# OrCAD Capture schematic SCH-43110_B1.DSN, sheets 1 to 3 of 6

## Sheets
1 5.Sensor, CAN, LIN,  Misc: size C; title: X-FRDM-KW38A; rev: B1; company: NXP Semiconductors; note: SCH-43110_B PDF: SPF-43110_B; note: 6501 William Cannon Drive West; note: Austin, TX 78735-8598
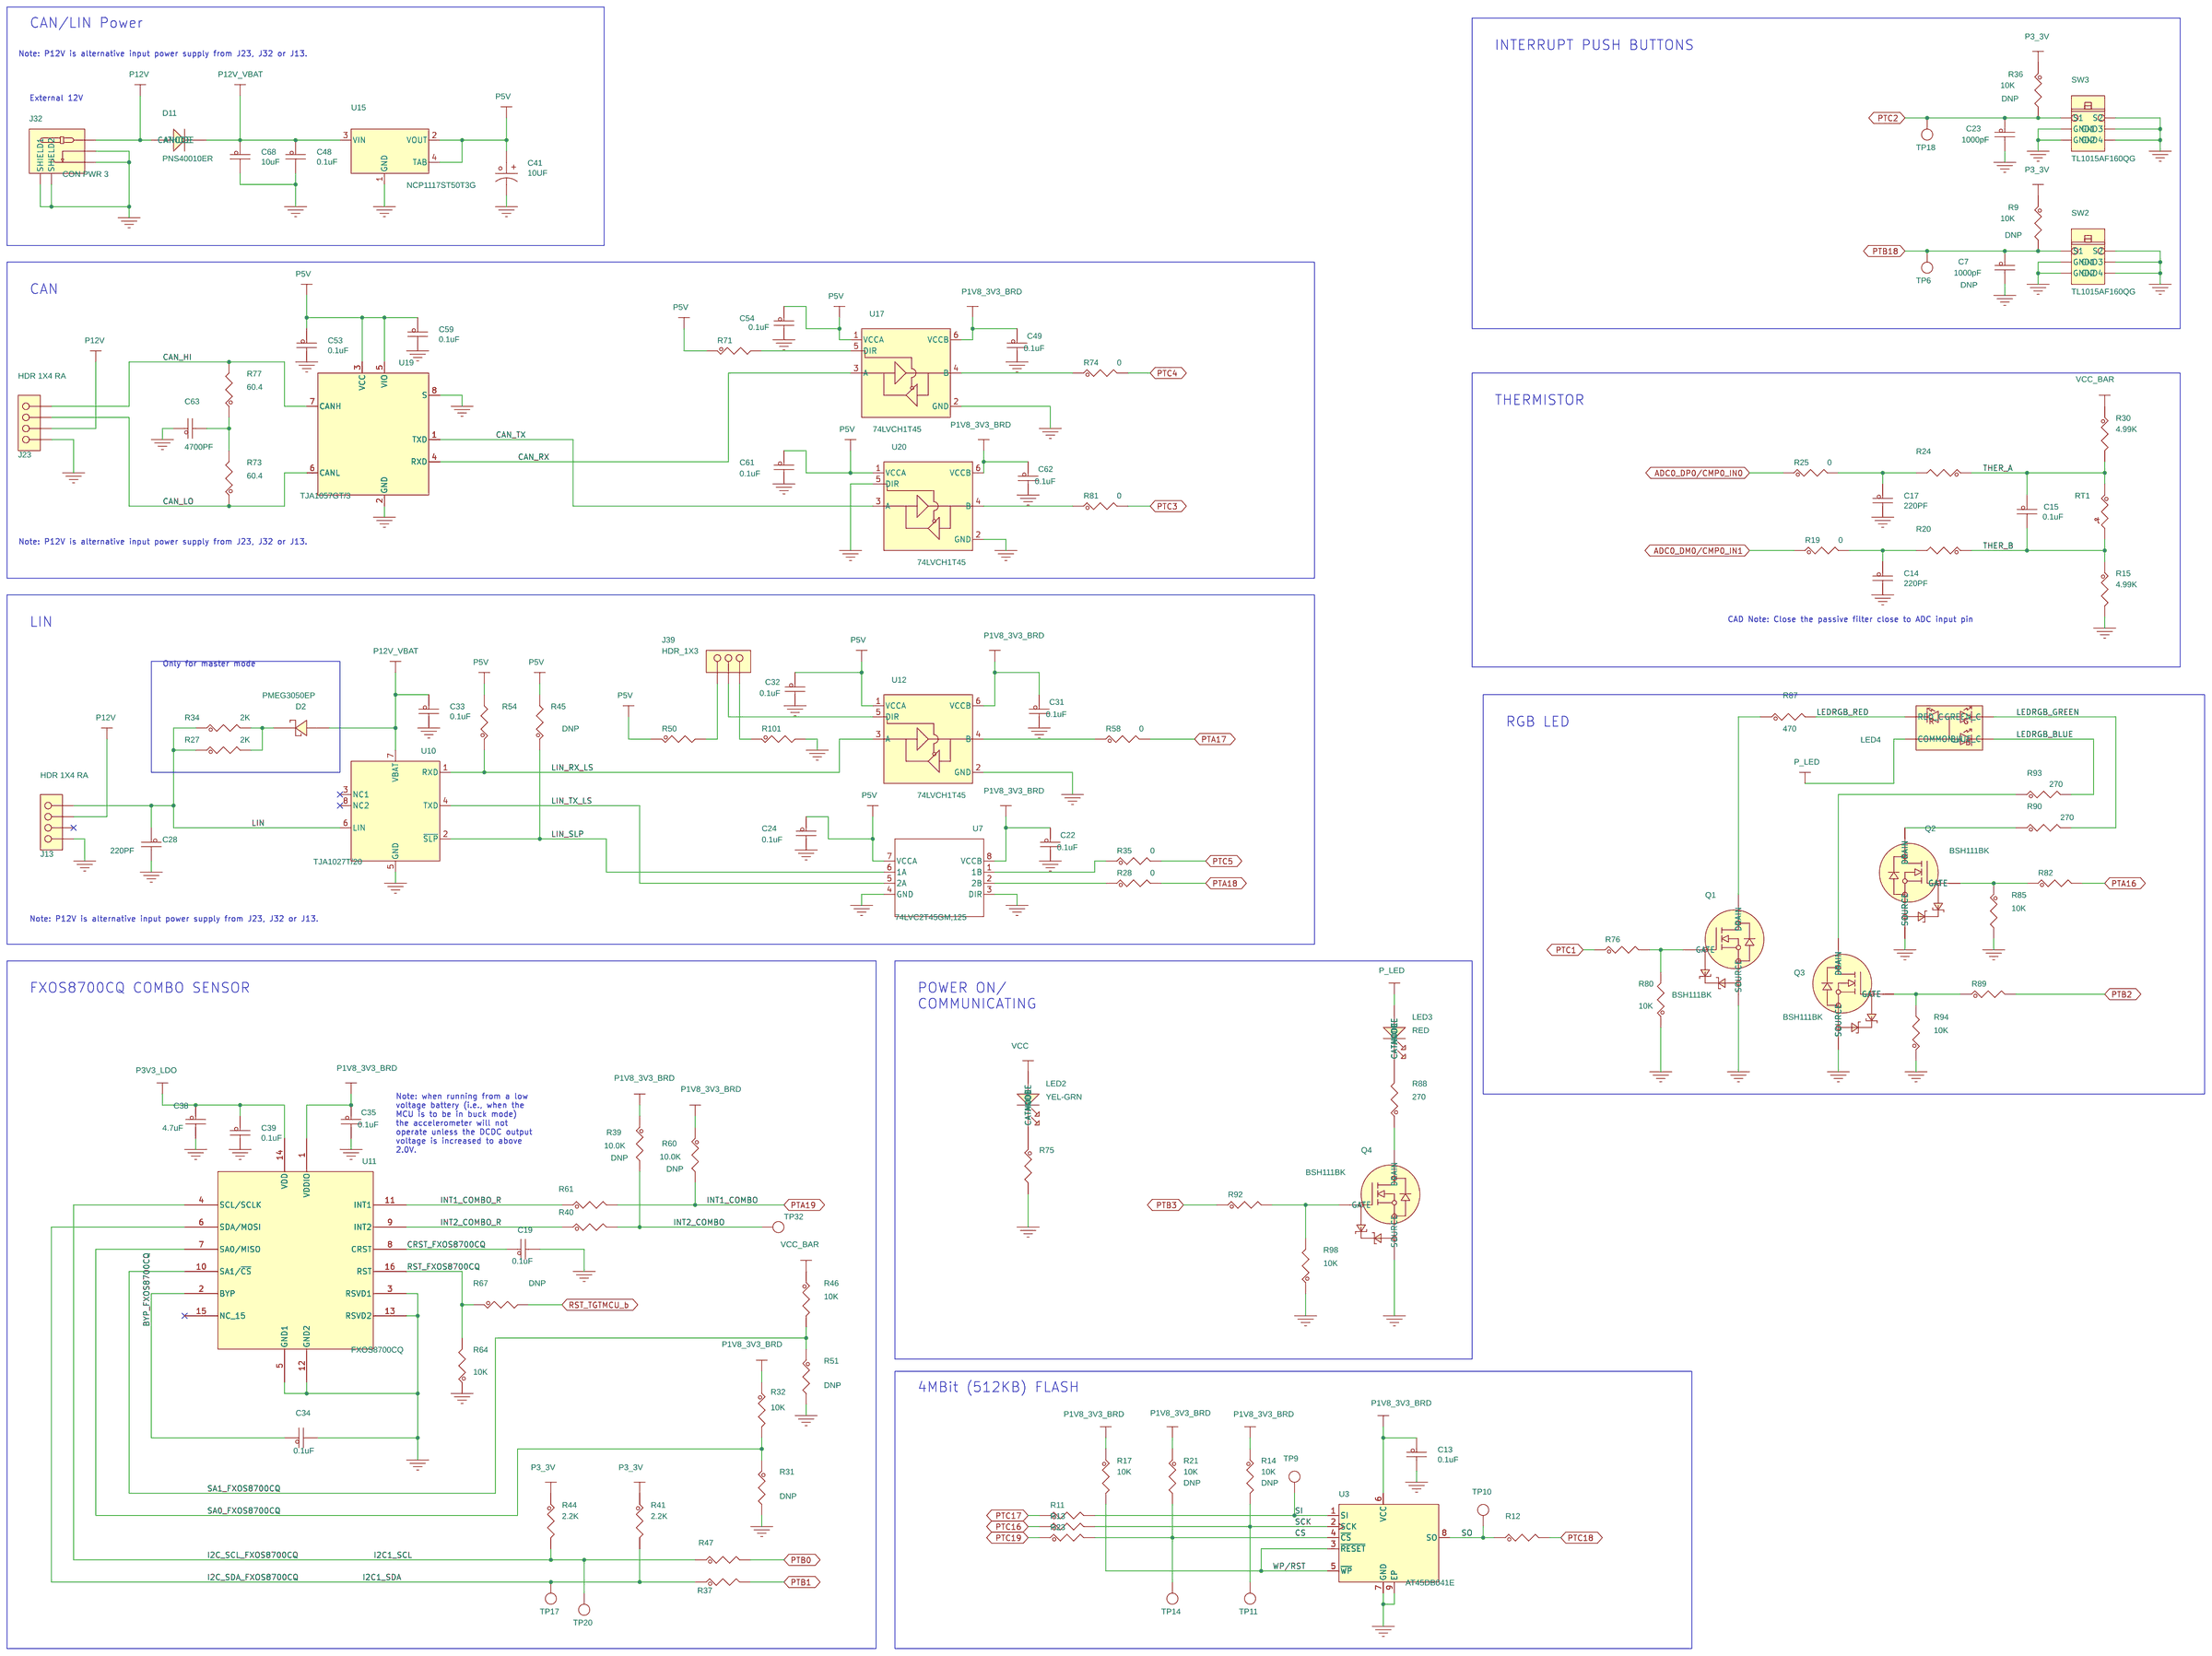
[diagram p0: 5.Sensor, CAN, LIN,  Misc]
2 1. Title Page
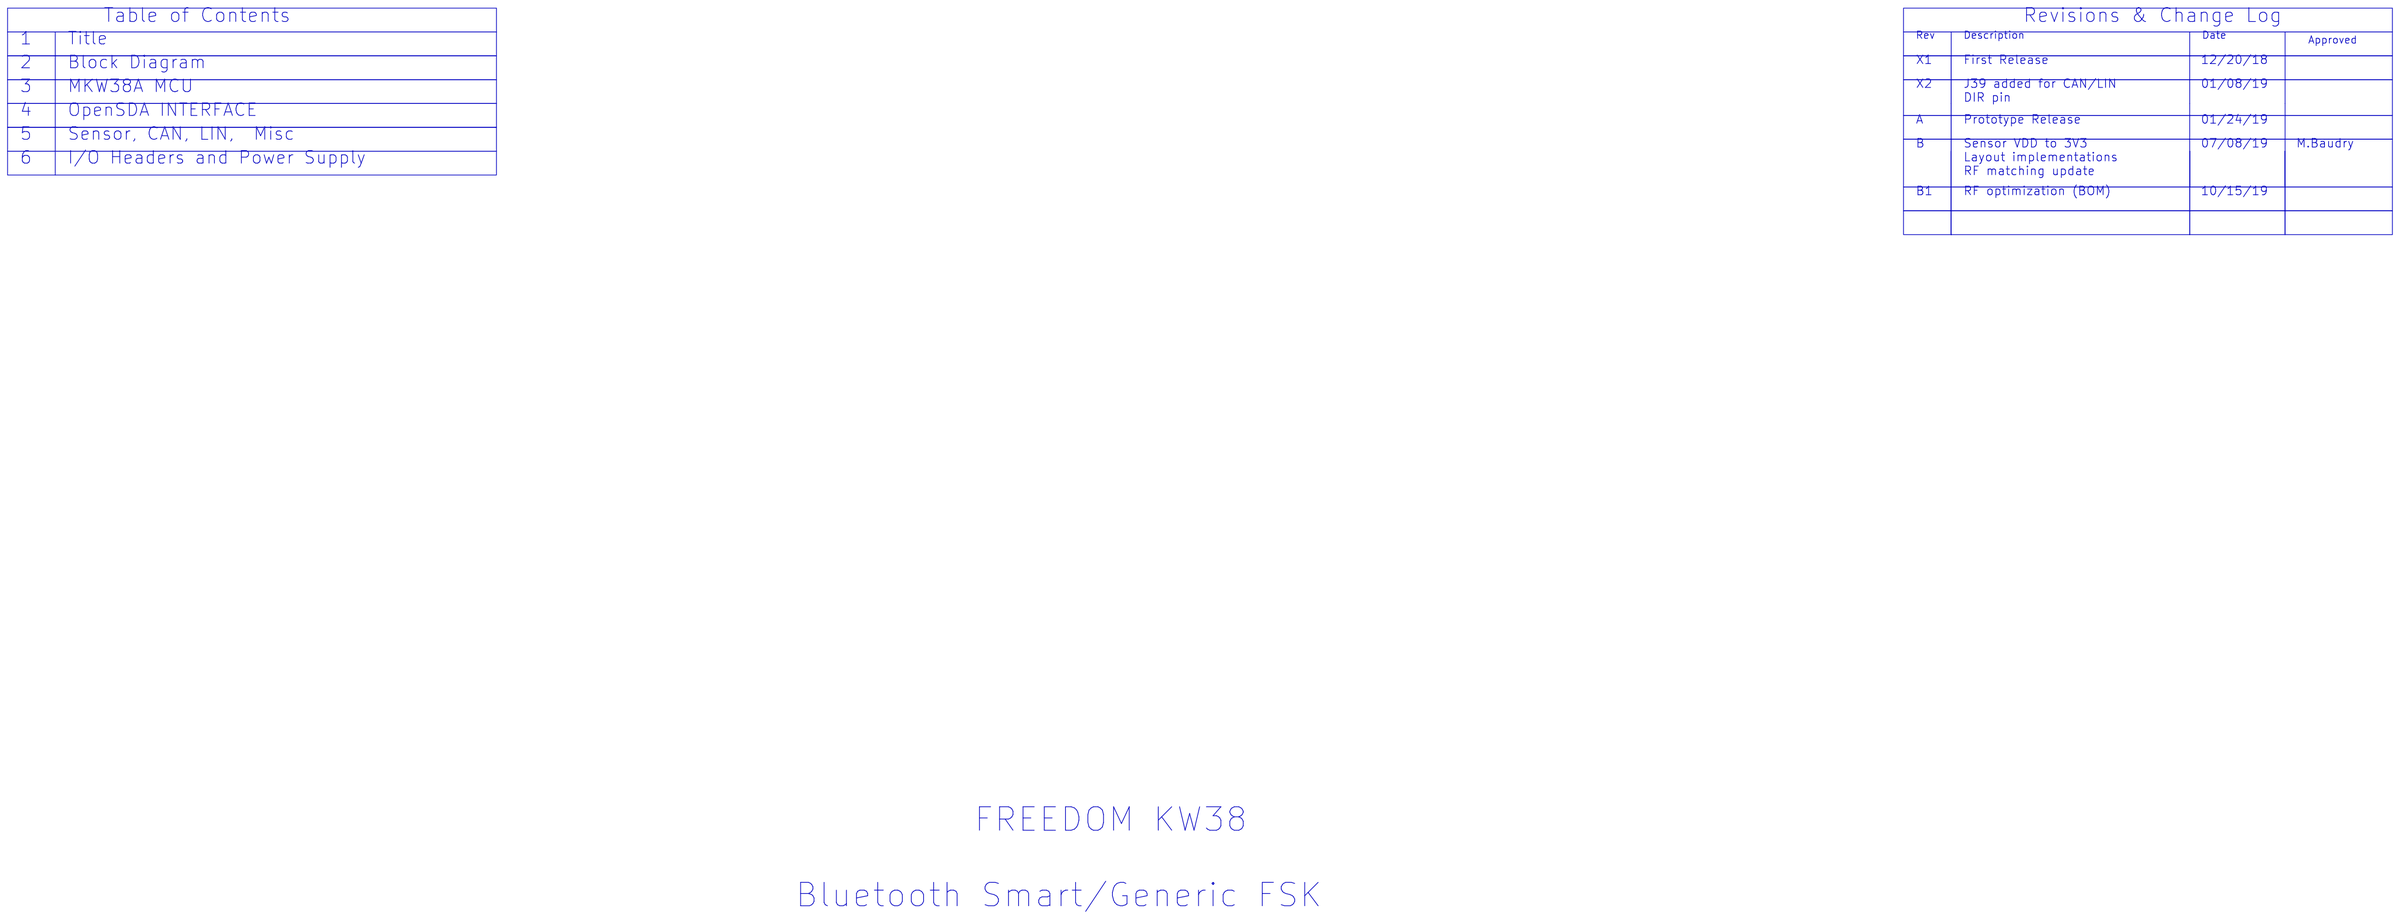
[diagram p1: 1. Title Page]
3 4. OpenSDA interface: size Custom
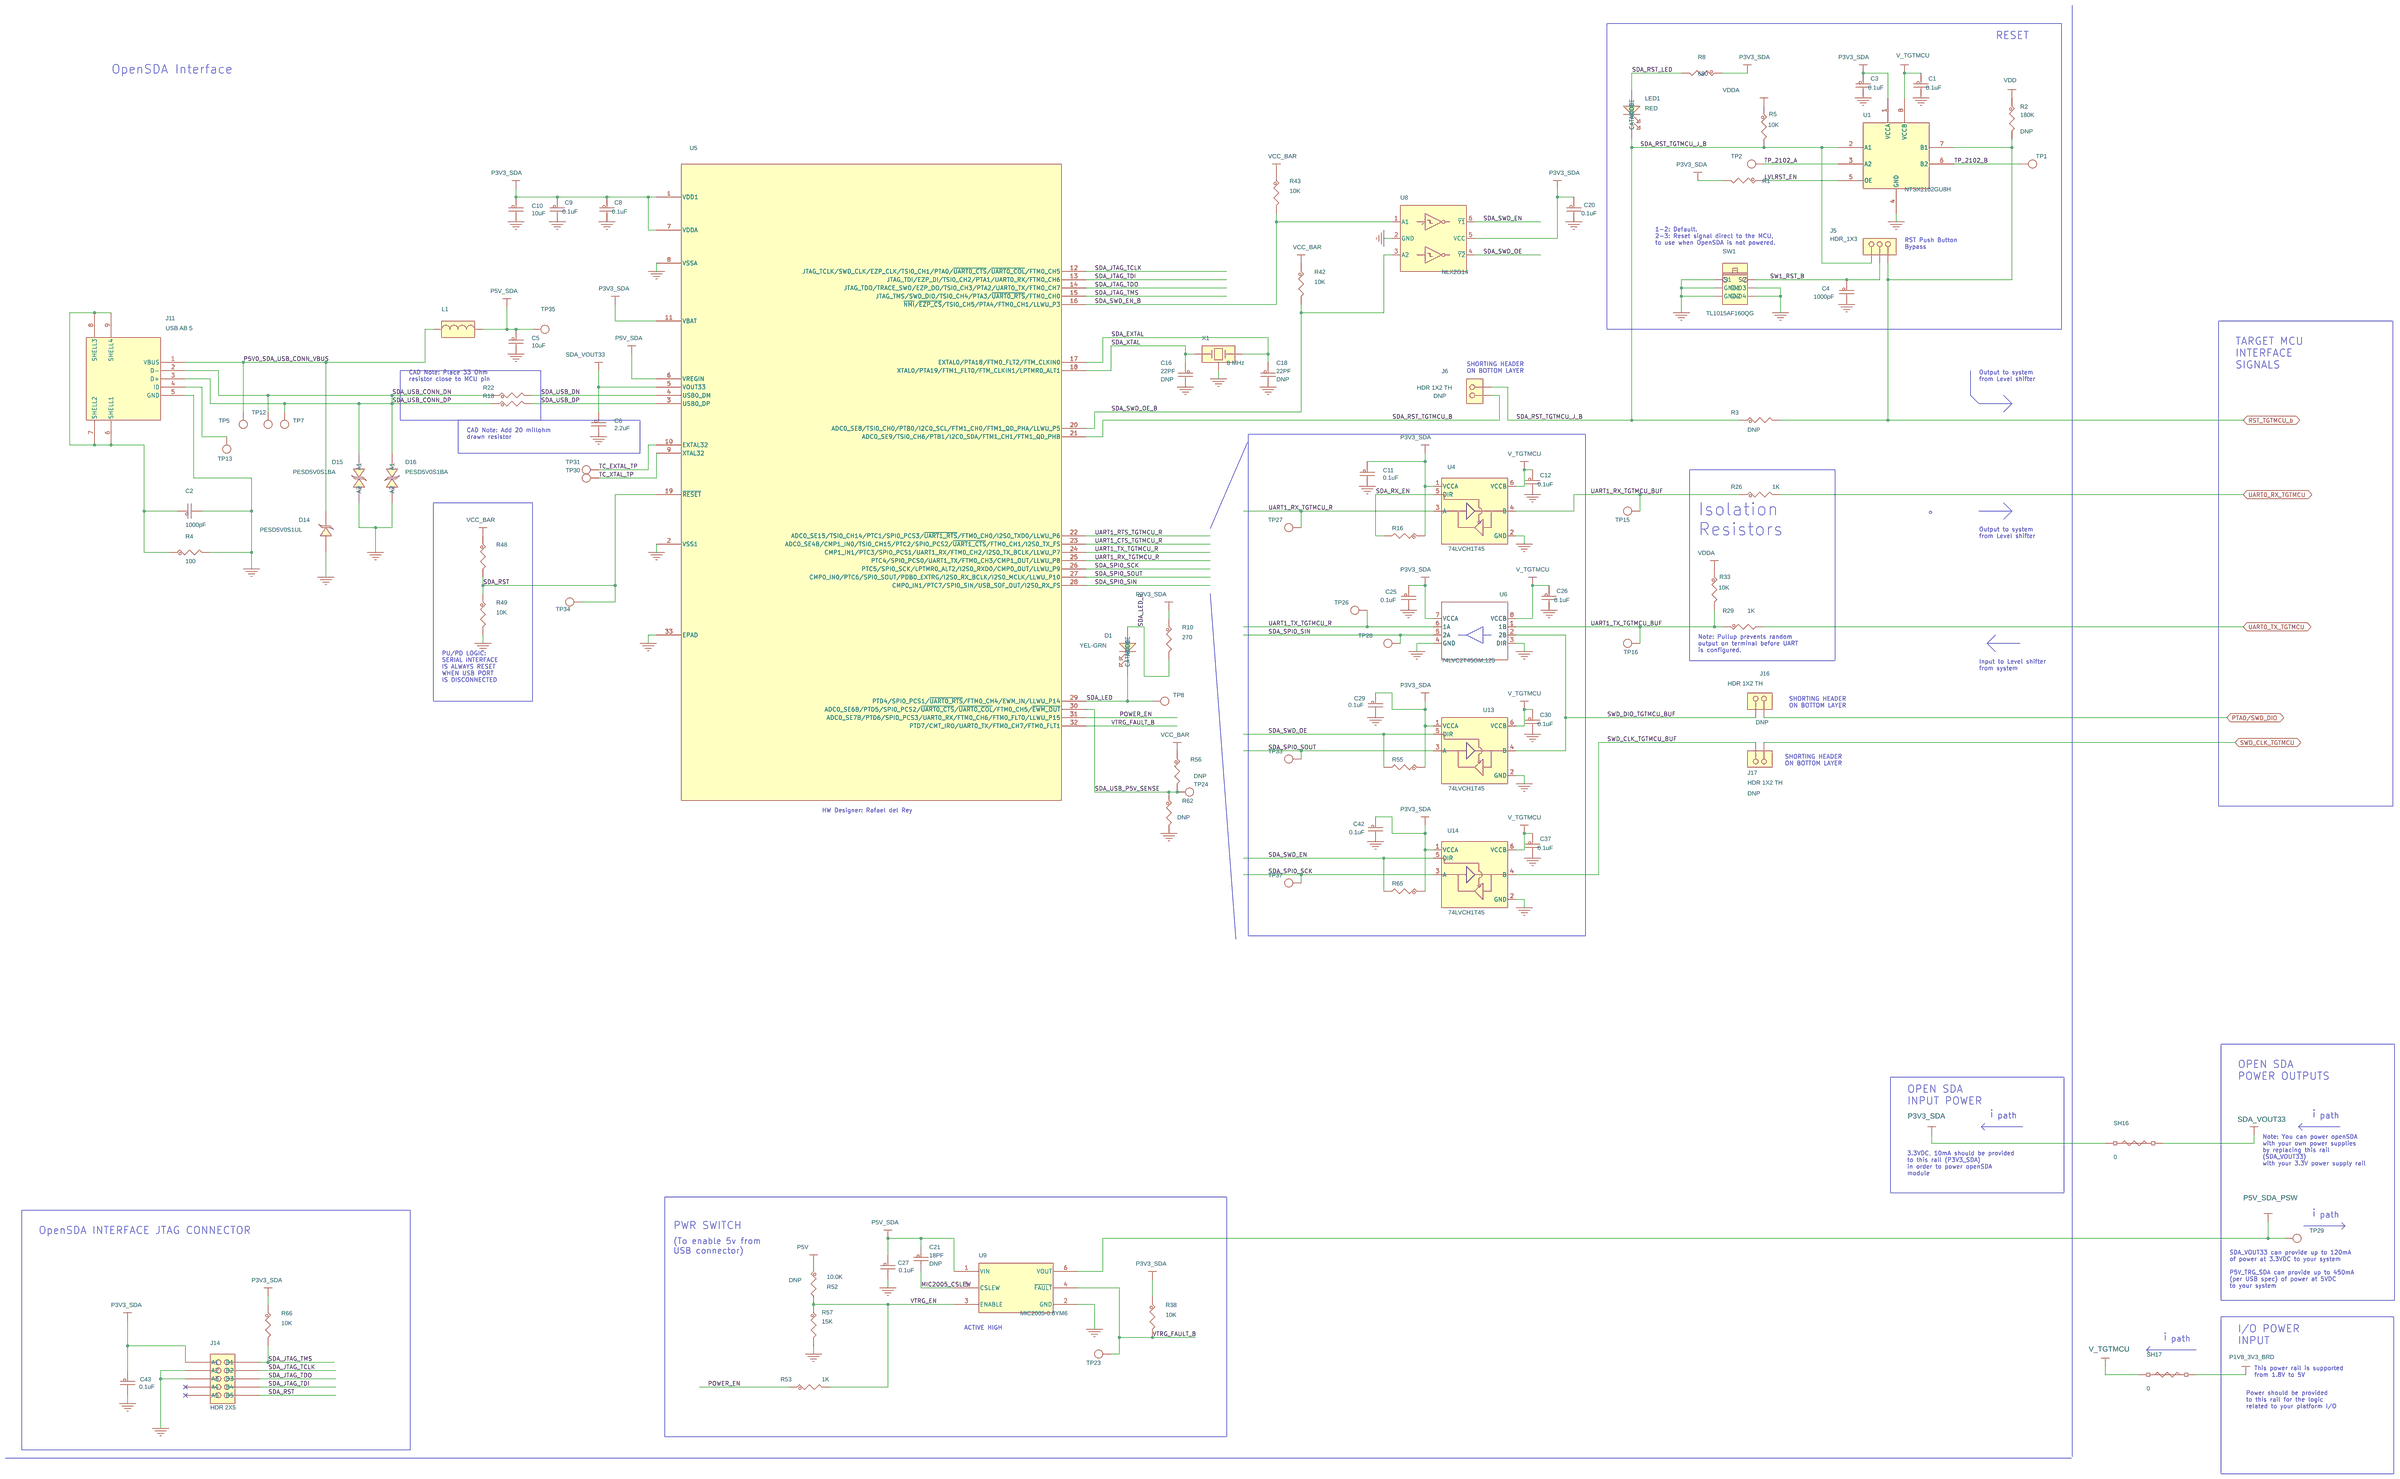
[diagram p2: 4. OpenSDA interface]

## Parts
sheet 4. OpenSDA interface
C1  0.1uF  [CC0402_25]
C2  1000pF  [CC0402_25]
C3  0.1uF  [CC0402_25]
C4  1000pF  [CC0402_25]
C5  10uF  [CC0603_OV]
C6  2.2uF  [CC0603_OV]
C8  0.1uF  [CC0402_25]
C9  0.1uF  [CC0402_25]
C10  10uF  [CC0603_OV]
C11  0.1uF  [CC0402_25]
C12  0.1uF  [CC0402_25]
C16  22PF  [CC0402_25]
C18  22PF  [CC0402_25]
C20  0.1uF  [CC0402_25]
C21  18PF  [CC0603_OV]
C25  0.1uF  [CC0402_25]
C26  0.1uF  [CC0402_25]
C27  0.1uF  [CC0402_25]
C29  0.1uF  [CC0402_25]
C30  0.1uF  [CC0402_25]
C37  0.1uF  [CC0402_25]
C42  0.1uF  [CC0402_25]
C43  0.1uF  [CC0402_25]
D1  YEL-GRN  [LED_0603]
D14  PESD5V0S1UL  [sod-882]
D15  PESD5V0S1BA  [sod323_bid]
D16  PESD5V0S1BA  [sod323_bid]
J5  HDR_1X3  [HDR103]
J6  HDR 1X2 TH  [SH_HDR102_BOTTOM]
J11  USB AB 5  [con9_microAB_usb_shell_th]
J14  HDR 2X5  [hdr_2X5_6x3_1p27mm_th]
J16  HDR 1X2 TH  [SH_HDR102_BOTTOM]
J17  HDR 1X2 TH  [SH_HDR102_BOTTOM]
L1  330 OHM  [IND_0805]
LED1  RED  [led_0603]
R1  4.7K  [RC0402_25]
R2  180K  [RC0402_25]
R3  0  [RC0402_25]
R4  100  [RC0402_25]
R5  10K  [RC0402_25]
R8  680  [RC0402_25]
R10  270  [RC0402_25]
R16  4.7K  [RC0402_25]
R18  33  [RC0402_25]
R22  33  [RC0402_25]
R26  1K  [RC0402_25]
R29  1K  [RC0402_25]
R33  10K  [RC0402_25]
R38  10K  [RC0402_25]
R42  10K  [RC0402_25]
R43  10K  [RC0402_25]
R48  4.7K  [RC0402_25]
R49  10K  [RC0402_25]
R52  10.0K  [RC0402_25]
R53  1K  [RC0402_25]
R55  4.7K  [RC0402_25]
R56  4.7K  [RC0402_25]
R57  15K  [RC0402_25]
R62  10.0K  [RC0402_25]
R65  4.7K  [RC0402_25]
R66  10K  [RC0402_25]
SH16  0  [SH0603]
SH17  0  [SH0603]
SW1  TL1015AF160QG  [sw2_spst_4x3_sm]
TP1  TPAD_030  [TPAD_030]
TP2  TPAD_030  [TPAD_030]
TP5  TPAD_020  [tpad_020]
TP7  TPAD_020  [tpad_020]
TP8  TPAD_040  [TPAD_040]
TP12  TPAD_020  [tpad_020]
TP13  TPAD_020  [tpad_020]
TP15  TPAD_030  [TPAD_030]
TP16  TPAD_030  [TPAD_030]
TP23  TPAD_030  [TPAD_030]
TP24  TPAD_030  [TPAD_030]
TP26  TPAD_030  [TPAD_030]
TP27  TPAD_030  [TPAD_030]
TP28  TPAD_030  [TPAD_030]
TP29  TPAD_040  [TPAD_040]
TP30  TPAD_030  [TPAD_030]
TP31  TPAD_030  [TPAD_030]
TP33  TPAD_030  [TPAD_030]
TP34  TPAD_040  [TPAD_040]
TP35  TPAD_020  [tpad_020]
TP37  TPAD_030  [TPAD_030]
U1  NTSX2102GU8H  [xqfn8_1p45x1p25mm]
U4  74LVCH1T45  [udfn6_1x1p5mm]
U5  MK20DX128VFM5  [QFN32_S142EP]
U6  74LVC2T45GM,125  [qfn8_1p6x1p6mm]
U8  NLX2G14  [udfn6_1p45x1_0p5mm]
U9  MIC2005-0.8YM6  [SOT23-6_a]
U13  74LVCH1T45  [udfn6_1x1p5mm]
U14  74LVCH1T45  [udfn6_1x1p5mm]
X1  8 MHz  [XTAL3_3P35X1P45_SM]
sheet 5.Sensor, CAN, LIN,  Misc
C7  1000pF  [CC0402_25]
C13  0.1uF  [CC0402_25]
C14  220PF  [CC0402_25]
C15  0.1uF  [CC0402_25]
C17  220PF  [CC0402_25]
C19  0.1uF  [CC0402_25]
C22  0.1uF  [CC0402_25]
C23  1000pF  [CC0402_25]
C24  0.1uF  [CC0402_25]
C28  220PF  [CC0603_OV]
C31  0.1uF  [CC0402_25]
C32  0.1uF  [CC0402_25]
C33  0.1uF  [CC0402_25]
C34  0.1uF  [CC0402_25]
C35  0.1uF  [CC0402_25]
C38  4.7uF  [CC0402_25]
C39  0.1uF  [CC0402_25]
C41  10UF  [CC3216]
C48  0.1uF  [CC0402_25]
C49  0.1uF  [CC0402_25]
C53  0.1uF  [CC0402_25]
C54  0.1uF  [CC0402_25]
C59  0.1uF  [CC0402_25]
C61  0.1uF  [CC0402_25]
C62  0.1uF  [CC0402_25]
C63  4700PF  [CC0603_OV]
C68  10uF  [CC0603_OV]
D2  PMEG3050EP  [sod-128]
D11  PNS40010ER  [sod123w]
J13  HDR 1X4 RA  [con_hdr_4m_100_th_ra]
J23  HDR 1X4 RA  [con_hdr_4m_100_th_ra]
J32  CON PWR 3  [con3_pwr_jack_th_pj051a]
J39  HDR_1X3  [HDR103]
LED2  YEL-GRN  [LED_0603]
LED3  RED  [led_2p_0805]
LED4  CLV1A-FKB-CK1vw1de1BB7C3C3  [led4_3p4x3mm_smt]
Q1  BSH111BK  [SOT23_A]
Q2  BSH111BK  [SOT23_A]
Q3  BSH111BK  [SOT23_A]
Q4  BSH111BK  [SOT23_A]
R9  10K  [RC0402_25]
R11  0  [RC0402_25]
R12  0  [RC0402_25]
R13  0  [RC0402_25]
R14  10K  [RC0402_25]
R15  4.99K  [RC0402_25]
R17  10K  [RC0402_25]
R19  0  [RC0603_OV]
R20  100  [RC0402_25]
R21  10K  [RC0402_25]
R23  0  [RC0402_25]
R24  100  [RC0402_25]
R25  0  [RC0603_OV]
R27  2K  [RC0805_OV]
R28  0  [RC0402_25]
R30  4.99K  [RC0402_25]
R31  0  [RC0402_25]
R32  10K  [RC0402_25]
R34  2K  [RC0805_OV]
R35  0  [RC0402_25]
R36  10K  [RC0402_25]
R37  0  [RC0402_25]
R39  10.0K  [RC0402_25]
R40  0  [RC0402_25]
R41  2.2K  [RC0402_25]
R44  2.2K  [RC0402_25]
R45  4.7K  [RC0402_25]
R46  10K  [RC0402_25]
R47  0  [RC0402_25]
R50  4.7K  [RC0402_25]
R51  0  [RC0402_25]
R54  4.7K  [RC0402_25]
R58  0  [RC0402_25]
R60  10.0K  [RC0402_25]
R61  0  [RC0402_25]
R64  10K  [RC0402_25]
R67  0  [RC0402_25]
R71  4.7K  [RC0402_25]
R73  60.4  [RC0805_OV]
R74  0  [RC0402_25]
R75  220  [RC0603_OV]
R76  0  [RC0402_25]
R77  60.4  [RC0805_OV]
R80  10K  [RC0402_25]
R81  0  [RC0402_25]
R82  0  [RC0402_25]
R85  10K  [RC0402_25]
R87  470  [RC0402_25]
R88  270  [RC0402_25]
R89  0  [RC0402_25]
R90  270  [RC0402_25]
R92  0  [RC0402_25]
R93  270  [RC0402_25]
R94  10K  [RC0402_25]
R98  10K  [RC0402_25]
R101  4.7K  [RC0402_25]
RT1  10K  [RC0603_OV]
SW2  TL1015AF160QG  [sw2_spst_4x3_sm]
SW3  TL1015AF160QG  [sw2_spst_4x3_sm]
TP6  TPAD_030  [TPAD_030]
TP9  TPAD_030  [TPAD_030]
TP10  TPAD_030  [TPAD_030]
TP11  TPAD_030  [TPAD_030]
TP14  TPAD_030  [TPAD_030]
TP17  TPAD_030  [TPAD_030]
TP18  TPAD_030  [TPAD_030]
TP20  TPAD_030  [TPAD_030]
TP32  TPAD_030  [TPAD_030]
U3  AT45DB041E  [dfn8_1p27_6x5mm_3p6x4p2]
U7  74LVC2T45GM,125  [qfn8_1p6x1p6mm]
U10  TJA1027T/20  [so8_1p27_4x5]
U11  FXOS8700CQ  [QFN5X3_0P5_3X3]
U12  74LVCH1T45  [udfn6_1x1p5mm]
U15  NCP1117ST50T3G  [sot223]
U17  74LVCH1T45  [udfn6_1x1p5mm]
U19  TJA1057GT/3  [SO8_1P27_4X5]
U20  74LVCH1T45  [udfn6_1x1p5mm]

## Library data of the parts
C1 C3 C8 C9 C11-C13 C15 C19 C20 C22 C24-C27 C29-C35 C37 C39 C42 C43 C49 C53 C54 C59 C61 C62 = CAP_NP: CAP CER 0.1uF 50V 10% X7R 0402; AGILE_PN: 150-79069; CAD_APPROVED: Yes; FPLIST: CC0402_25,CC0402_HD,0402_CC; HEIGHT: 0.55MM; MFG_NAME01: TDK; MFG_PN01: C1005X7R1H104K050BE; ROHS: Yes; Tolerance: 10%; VOLTAGE: 50V
C2 C4 C23 = CAP_NP: CAP CER 1000PF 50V 5% C0G 0402; AGILE_PN: 150-76334; CAD_APPROVED: Yes; FPLIST: CC0402_25,CC0402_HD,0402_CC; HEIGHT: 0.55MM; MFG_NAME01: MURATA; MFG_PN01: GRM1555C1H102JA01D; Package Size: 0402; Package Type: 180mm Paper Tape; ROHS: Yes; Tolerance: 5%; VOLTAGE: 50V
C5 C10 C68 = CAP_NP: CAP CER 10uF 16V 20% X5R 0603; AGILE_PN: 150-79092; CAD_APPROVED: Yes; FPLIST: CC0603_OV,CC0603,0603_CC; HEIGHT: 1mm; MFG_NAME01: TAIYO YUDEN; MFG_PN01: EMK107BBJ106MA-T; ROHS: Yes; Tolerance: 20%; VOLTAGE: 16V
C6 = CAP_NP: CAP CER 2.2UF 16V 10% X5R 0603; AGILE_PN: 150-75417; CAD_APPROVED: YES; FPLIST: CC0603_OV,CC0603,0603_CC; HEIGHT: 0.9 MM; MFG_NAME01: CAPAX TECHNOLOGIES INC.; MFG_PN01: 0603B225K160SNT; Package Size: 0603; ROHS: Yes; Tolerance: 10%; VOLTAGE: 16V
C16 C18 = CAP_NP: CAP CER 22PF 50V 5% C0G 0402; AGILE_PN: 150-75266; ASSY_OPT: DNP; CAD_APPROVED: Yes; FPLIST: CC0402_25,CC0402_HD,0402_CC; HEIGHT: 0.635MM; MFG_NAME01: WURTH ELEKTRONIK EISOS GMBH & CO. KG (ELECTRONIC & ELECTROMEHANICAL COMP); MFG_PN01: 885012005057; ROHS: Yes; Temp Range: -55°C to 125°C; Temp_Range: -55°C to 125°C; Tolerance: 5%; VOLTAGE: 50V
C21 = CAP_NP: CAP CER 18PF 50V 5% C0G 0603; AGILE_PN: 150-75116; ASSY_OPT: DNP; CAD_APPROVED: Yes; FPLIST: CC0603_OV,CC0603,0603_CC; HEIGHT: 0.90MM; MFG_NAME01: YAGEO AMERICA; MFG_PN01: CC0603JRNPO9BN180; Package Size: 0603; Package Type: SMT; ROHS: Yes; TOL: 5%; Tolerance: 5%; VOLTAGE: 50V
D1 LED2 = LED: LED SUPER YEL/GRN SGL 25MA SMD 0603; AGILE_PN: 370-76693; CAD_APPROVED: Yes; HEIGHT: 0.7MM; MFG_NAME01: EVERLIGHT INTERNATIONAL CORPORATION; MFG_PN01: 19-213SYGC/S454/TR8; ROHS: Yes; VOLTAGE: 5V
D14 = DIODE_TVS: DIODE TVS UNIDIR 5V AEC-Q101 SOD882; AGILE_PN: 480-79614; CAD_APPROVED: Yes; HEIGHT: 0.5MM; MFG_NAME01: NEXPERIA; MFG_PN01: PESD5V0S1UL,315; ROHS: Yes
D15 D16 = DIODE_TVS_BIDIR: DIODE BIDIR ESD PROT 5V SOD323; AGILE_PN: 480-77497; CAD_APPROVED: Yes; HEIGHT: 1.1 MM; MFG_NAME01: PHILIPS SEMICONDUCTOR; ROHS: Yes
J5 J39 = CONN_HDR_3X1: HDR 1X3 TH 100MIL SP 350H AU 118L; AGILE_PN: 210-81176; CAD_APPROVED: Yes; HEIGHT: 8.9MM; MFG_NAME01: LIANYI DIANZI; MFG_PN01: 313103S1411; Package Size: 7p62x2p54x8p9mm; Package Type: TH; ROHS: Yes
J6 J16 J17 = CONN_HDR_2X1: HDR 1X2 TH 100MIL SP 339H AU 98L; AGILE_PN: 210-75439; ASSY_OPT: DNP; CAD_APPROVED: YES; FPLIST: HDR102,SH_HDR102_BOTTOM; HEIGHT: 8.71 MM; MFG_NAME01: SAMTEC; MFG_PN01: TSW-102-07-G-S; ROHS: Yes; Temp Range: -55°C to +125°C; Temp_Range: -55°C to +125°C
J11 = MICRO_USB_CONN_9PIN: CON 5 USB MICRO-AB RA SKT SMT 0.65MM SP AU; AGILE_PN: 211-78692; CAD_APPROVED: Yes; HEIGHT: 2.8MM; MFG_NAME01: Hirose; MFG_PN01: ZX62D-AB-5P8(30); ROHS: Yes
J14 = CONN_HDR_5X2: HDR 2X5 TH 50MIL CTR 264H AU 91L; AGILE_PN: 210-81148; CAD_APPROVED: Yes; HEIGHT: 6.7MM; MFG_NAME01: LIANYI DIANZI; MFG_PN01: 333210S1411; ROHS: Yes
L1 = BEAD: IND FER BEAD 330OHM@100MHZ 2.5A -- SMT; AGILE_PN: 180-30021; CAD_APPROVED: YES; HEIGHT: 1.05 MM; MFG_NAME01: TDK; MFG_PN01: MPZ2012S331AT000; PART_TYPE: FERRITE; ROHS: Yes; Temp Range: -55°C to +125°C; Temp_Range: -55°C to +125°C; Tolerance: 25%
LED1 = LED: LED ULTRA BRIGHT RED SGL 25MA SMT 0603; AGILE_PN: 370-76692; CAD_APPROVED: Yes; HEIGHT: 0.7 MM; MFG_NAME01: EVERLIGHT INTERNATIONAL CORPORATION; MFG_PN01: 19-213/R6C-AP1Q2B/3T; ROHS: Yes
R1 R16 R48 R50 R54 R55 R65 R71 R101 = RES: RES MF 4.7K 1/16W 5% 0402; AGILE_PN: 470-75626; CAD_APPROVED: Yes; FPLIST: RC0402_25,RC0402_HD,0402_CC; HEIGHT: 0.41mm; MFG_NAME01: NIC COMPONENTS CORP; MFG_PN01: NRCL04J472TRF; ROHS: Yes; TOL: 1%; Tolerance: 5%
R2 = RES: RES MF 180K 1/16W 1% 0402; AGILE_PN: 470-81163; ASSY_OPT: DNP; CAD_APPROVED: Yes; FPLIST: RC0402_25,RC0402_HD,0402_CC; HEIGHT: 0.4 MM; MFG_NAME01: YAGEO AMERICA; MFG_PN01: RC0402FR-07180KL; ROHS: Yes; VOLTAGE: 50 V
R3 = RES: RES MF ZERO OHM 1/16W 5% 0402; AGILE_PN: 470-75394; ASSY_OPT: DNP; CAD_APPROVED: Yes; FPLIST: RC0402_25,RC0402_HD,RC0402_X2,0402_CC; HEIGHT: 0.45 MM; MFG_NAME01: ROHM; MFG_PN01: MCR01MZPJ000; ROHS: Yes; TOL: 5%; Tolerance: 5%; VOLTAGE: 1/16W
R4 = RES: RES MF 100 OHM 1/16W 1% 0402; AGILE_PN: 470-30454; CAD_APPROVED: Yes; FPLIST: RC0402_25,RC0402_HD,0402_CC; HEIGHT: 0.4 MM; MFG_NAME01: THYE MING TECH CO LTD; MFG_PN01: CR-02FL6--100R; ROHS: Yes; Tolerance: 1%; VOLTAGE: 50V
R5 R17 R32 R33 R38 R42 R43 R46 R49 R64 R66 R80 R85 R94 R98 = RES: RES MF 10K 1/16W 1% 0402; AGILE_PN: 470-80452; CAD_APPROVED: Yes; FPLIST: RC0402_25,RC0402_HD,0402_CC; HEIGHT: 0.40 MM; MFG_NAME01: NIC COMPONENTS CORP; MFG_PN01: NRCL04F1002TRF; ROHS: Yes; Tolerance: 1%
R8 = RES: RES MF 680 OHM 1/16W 5% 0402; AGILE_PN: 470-77301; CAD_APPROVED: Yes; FPLIST: RC0402_25,RC0402_HD,0402_CC; HEIGHT: 0.4MM; MFG_NAME01: PANASONIC; MFG_PN01: ERJ-2GEJ681X; ROHS: Yes; Tolerance: 5%; VOLTAGE: 50V
R10 R88 R90 R93 = RES: RES TF 270 OHM 1/16W 1% 0402; AGILE_PN: 470-81305; CAD_APPROVED: Yes; FPLIST: RC0402_25,RC0402_HD,0402_CC; HEIGHT: 0.4MM; MFG_NAME01: YAGEO; MFG_PN01: RC0402FR-07270RL; ROHS: Yes; Temp Range: -55°C to +155°C; Temp_Range: -55°C to +155°C; Tolerance: 1%; VOLTAGE: 50V
R18 R22 = RES: RES MF 33.0 OHM 1/16W 1% 0402; AGILE_PN: 470-75790; CAD_APPROVED: Yes; FPLIST: RC0402_25,RC0402_HD,RC0402_X2,0402_CC; HEIGHT: 0.4MM; MFG_NAME01: THYE MING TECH CO LTD; MFG_PN01: CR-02FL6---33R; ROHS: Yes; Tolerance: 1%
R26 R29 R53 = RES: RES MF 1.0K 1/16W 5% 0402; AGILE_PN: 470-75555; CAD_APPROVED: Yes; FPLIST: RC0402_25,RC0402_HD,RC0402_X2,0402_CC; HEIGHT: 0.41mm; MFG_NAME01: VISHAY INTERTECHNOLOGY; MFG_PN01: CRCW04021K00JNED; ROHS: Yes; Tolerance: 5%
R52 = RES: RES MF 10.0K 1/16W 1% AEC-Q200 0402; AGILE_PN: 470-75416; ASSY_OPT: DNP; CAD_APPROVED: Yes; FPLIST: RC0402_25,RC0402_HD,0402_CC; HEIGHT: 0.4MM; MFG_NAME01: KOA SPEER; MFG_PN01: RK73H1ETTP1002F; ROHS: Yes; TOL: 1%; Temp Range: –55 °C to +155 °C; Temp_Range: –55 °C to +155 °C; Tolerance: 1%
R45 R56 = RES: RES MF 4.7K 1/16W 5% 0402; AGILE_PN: 470-75626; ASSY_OPT: DNP; CAD_APPROVED: Yes; FPLIST: RC0402_25,RC0402_HD,0402_CC; HEIGHT: 0.41mm; MFG_NAME01: NIC COMPONENTS CORP; MFG_PN01: NRCL04J472TRF; ROHS: Yes; TOL: 1%; Tolerance: 5%
R57 = RES: RES MF 15.0K 1/16W 1% 0402; AGILE_PN: 470-76066; CAD_APPROVED: Yes; FPLIST: RC0402_25,RC0402_HD,0402_CC; HEIGHT: 0.4 MM; MFG_NAME01: NIC COMPONENTS CORP; MFG_PN01: NRCL04F1502TRF; ROHS: Yes; Tolerance: 1%
R62 = RES: RES MF 10.0K 1/16W 1% AEC-Q200 0402; AGILE_PN: 470-75416; ASSY_OPT: DNP; CAD_APPROVED: Yes; FPLIST: RC0402_25,RC0402_HD,0402_CC; HEIGHT: 0.4MM; MFG_NAME01: KOA SPEER; MFG_PN01: RK73H1ETTP1002F; ROHS: Yes; Temp Range: –55 °C to +155 °C; Temp_Range: –55 °C to +155 °C; Tolerance: 1%
SH16 SH17 = RES_SHORT-2: ZERO OHM CUT TRACE 0603 PADS; NO PART TO ORDER; AGILE_PN: 470-80018; CAD_APPROVED: Yes; FPLIST: SH0603,SH0603_CC,SH0603-X2_PIN1TO2,SH0603-X2_PIN2TO3; HEIGHT: 0.1MM; MFG_NAME01: LAYOUT ELEMENT ONLY; MFG_PN01: LAYOUT ELEMENT ONLY; ROHS: Yes
SW1-SW3 = SW_SPNO_2P_GND6P: SW SPST PB 50MA 12V SMT; AGILE_PN: 510-77720; CAD_APPROVED: Yes; HEIGHT: 2.4MM; MFG_NAME01: E SWITCH; ROHS: Yes
TP1 TP2 TP6 TP9-TP11 TP14-TP18 TP20 TP23 TP24 TP26-TP28 TP30-TP33 TP37 = TESTLOOP: TEST POINT PAD 30MIL DIA SMT, NO PART TO ORDER; AGILE_PN: 211-76642; CAD_APPROVED: Yes; HEIGHT: 0.1MM; MFG_NAME01: NOTACOMPONENT; MFG_PN01: NOTACOMPONENT; ROHS: Yes
TP5 TP7 TP12 TP13 TP35 = TESTLOOP: TEST POINT PAD 0.5MM DIA SMT, NO PART TO ORDER; AGILE_PN: 211-77484; CAD_APPROVED: Yes; HEIGHT: 0.1MM; ROHS: Yes
TP8 TP29 TP34 = TESTLOOP: TEST POINT PAD 40MIL DIA SMT, NO PART TO ORDER; AGILE_PN: 211-76643; CAD_APPROVED: Yes; HEIGHT: 0.1MM; MFG_NAME01: NOTACOMPONENT; MFG_PN01: NOTACOMPONENT; ROHS: Yes
U1 = NTSX2102GD: IC DUAL SUPPLY XCVR 50 MBPS 5.5V XQFN8; AGILE_PN: 312-80763; CAD_APPROVED: Yes; HEIGHT: 0.5MM; MFG_NAME01: NXP SEMICONDUCTORS; ROHS: Yes; VOLTAGE: 5.5V
U4 U12-U14 U17 U20 = 74LVCH1T45_6P: IC XCVR 1BIT 3-STATE DUAL 1.2-5.5V XSON6; AGILE_PN: 312-80758; CAD_APPROVED: Yes; HEIGHT: 0.5MM; MFG_NAME01: NEXPERIA; MFG_PN01: 74LVCH1T45GM,132; ROHS: Yes; VOLTAGE: 1.2-5.5V
U5 = PK20DX128V_QFN_32P: IC MCU FLASH 128KB 50MHZ 1.71-3.6V QFN32; AGILE_PN: 344-01231; CAD_APPROVED: Yes; HEIGHT: 1MM; MFG_NAME01: FREESCALE SEMICONDUCTOR; ROHS: Yes; VOLTAGE: 1.71-3.6V
U6 U7 = 74LVC2T45GM_8P: IC XCVR DUAL SUPPLY 1.2 -5.5V XQFN8; AGILE_PN: 312-80762; CAD_APPROVED: Yes; HEIGHT: 0.5MM; MFG_NAME01: NEXPERIA; ROHS: Yes; VOLTAGE: 5.5V
U8 = NLX2G14_6P: IC INV DUAL SCHMITT TRIGGER 1.65-5.5V UDFN6; AGILE_PN: 315-80556; CAD_APPROVED: Yes; HEIGHT: 0.55MM; MFG_NAME01: ON SEMICONDUCTOR; MFG_PN01: NLX2G14AMUTCG; ROHS: Yes; VOLTAGE: 1.65-5.5V
U9 = MIC2005-0.8YM6: IC LIN SW PWR 0.8A 2.5-5.5V SOT23-6; AGILE_PN: 315-79199; CAD_APPROVED: Yes; HEIGHT: 1.45MM; MFG_NAME01: MICREL; ROHS: Yes; VOLTAGE: 2.5-5.5V
X1 = XTAL_CS: XTAL 8.00MHZ RSN CERAMIC -- SMT; AGILE_PN: 230-78262; CAD_APPROVED: Yes; HEIGHT: 0.8 MM; MFG_NAME01: MURATA; MFG_PN01: CSTNE8M00G550000R0; ROHS: Yes; Temp Range: -40 to +85°C; Temp_Range: -40 to +85°C
C7 = CAP_NP: CAP CER 1000PF 50V 5% C0G 0402; AGILE_PN: 150-76334; ASSY_OPT: DNP; CAD_APPROVED: Yes; FPLIST: CC0402_25,CC0402_HD,0402_CC; HEIGHT: 0.55MM; MFG_NAME01: MURATA; MFG_PN01: GRM1555C1H102JA01D; Package Size: 0402; Package Type: 180mm Paper Tape; ROHS: Yes; Tolerance: 5%; VOLTAGE: 50V
C14 C17 = CAP_NP: CAP CER 220PF 50V 5% C0G 0402; AGILE_PN: 150-30297; CAD_APPROVED: Yes; FPLIST: CC0402_25,CC0402_HD,0402_CC; HEIGHT: 0.55MM; MFG_NAME01: KEMET; MFG_PN01: C0402C221J5GAC; Package Size: 0402; ROHS: Yes; Tolerance: 5%; VOLTAGE: 50V
C28 = CAP_NP: CAP CER 220PF 50V 5% C0G 0603; AGILE_PN: 150-75388; CAD_APPROVED: YES; FPLIST: CC0603_OV,CC0603,0603_CC; HEIGHT: 0.9 mm; MFG_NAME01: AVX; MFG_PN01: 06035A221JAT2A; Package Size: 0603; ROHS: Yes; Tolerance: 5%; VOLTAGE: 50V
C38 = CAP_NP: CAP CER 4.7UF 6.3V 20% X5R 0402; AGILE_PN: 150-78463; CAD_APPROVED: Yes; FPLIST: CC0402_25,CC0402_HD,0402_CC; HEIGHT: 0.65MM; MFG_NAME01: TDK; MFG_PN01: C1005X5R0J475M050BC; ROHS: Yes; Tolerance: 20%; VOLTAGE: 6.3V
C41 = CAP_POL: CAP TANT ESR=0.900 OHMS 10UF 10V 20% -- 3216-18; AGILE_PN: 150-75257; CAD_APPROVED: Yes; HEIGHT: 1.8MM; MFG_NAME01: AVX; MFG_PN01: TPSA106M010R0900; Package Size: 3216-18; Package Type: 7" T/R; ROHS: Yes; Tolerance: 20%; VOLTAGE: 10V
C48 = CAP_NP: CAP CER 0.1uF 50V 10% X7R 0402; AGILE_PN: 150-79069; CAD_APPROVED: Yes; FPLIST: CC0603_OV,CC0603,0603_CC; HEIGHT: 0.55MM; MFG_NAME01: TDK; MFG_PN01: C1005X7R1H104K050BE; ROHS: Yes; Tolerance: 10%; VOLTAGE: 50V
C63 = CAP_NP: CAP CER 4700PF 50V 10% X7R 0603; AGILE_PN: 150-30078; CAD_APPROVED: Yes; FPLIST: CC0603_OV,CC0603,0603_CC; HEIGHT: 0.90MM; MFG_NAME01: YAGEO AMERICA; MFG_PN01: CC0603KRX7R9BB472; ROHS: Yes; Tolerance: 10%; VOLTAGE: 50V
D2 = DIODE_SCHTKY: DIODE SCH RECT 5A 30V AEC-Q101 SOD128; AGILE_PN: 480-78776; CAD_APPROVED: Yes; HEIGHT: 1.1 MM; MFG_NAME01: NEXPERIA; MFG_PN01: PMEG3050EP,115; ROHS: Yes; VOLTAGE: 30 V
D11 = DIODE: DIODE RECT SW 1A 400V AEC-Q101 SOD123W; AGILE_PN: 480-79648; CAD_APPROVED: Yes; HEIGHT: 1.1MM; MFG_NAME01: NEXPERIA; MFG_PN01: PNS40010ER,115; ROHS: Yes
J13 J23 = CONN_HDR_4X1: HDR 1X4 TH RA 100MIL SP 268H AU 124L; AGILE_PN: 210-79929; CAD_APPROVED: Yes; HEIGHT: 6.81MM; MFG_NAME01: MOLEX; MFG_PN01: 0022122041; ROHS: Yes
J32 = DC_POWER_JACK_SHD: CON 3 PWR JACK RA TH 295H -- NI 98L; AGILE_PN: 210-79945; CAD_APPROVED: Yes; HEIGHT: 7.5MM; MFG_NAME01: CUI INC; MFG_PN01: PJ-051A; ROHS: Yes
LED3 = LED: LED RED CLEAR SGL 25MA SMT 0805; AGILE_PN: 370-76689; CAD_APPROVED: Yes; HEIGHT: 1.1MM; MFG_NAME01: EVERLIGHT INTERNATIONAL CORPORATION; MFG_PN01: 17-21SURC/S530-A2/TR8; ROHS: Yes
LED4 = CLV1A_LED_4P: LED RED BL GRN SGL 50/25/25mA SMT; AGILE_PN: 370-76799; CAD_APPROVED: Yes; HEIGHT: 2.1MM; MFG_NAME01: CREE, INC; ROHS: Yes; Temp Range: -40°C to 85°C; Temp_Range: -40°C to 85°C; VOLTAGE: 5V
Q1-Q4 = NMOS_2N7002BKW_3P: TRAN NMOS SW FET 55V 210mA SOT23; AGILE_PN: 480-79704; CAD_APPROVED: Yes; HEIGHT: 1.1MM; MFG_NAME01: NEXPERIA; MFG_PN01: BSH111BKR; ROHS: Yes
R9 R21 R36 = RES: RES MF 10K 1/16W 1% 0402; AGILE_PN: 470-80452; ASSY_OPT: DNP; CAD_APPROVED: Yes; FPLIST: RC0402_25,RC0402_HD,0402_CC; HEIGHT: 0.40 MM; MFG_NAME01: NIC COMPONENTS CORP; MFG_PN01: NRCL04F1002TRF; PRIORITY_PN: 006-00552; ROHS: Yes; TOL: 1%; Tolerance: 1%
R11-R13 R23 R37 R40 R47 R61 R76 R82 R89 R92 = RES: RES MF ZERO OHM 1/16W 5% 0402; AGILE_PN: 470-75394; CAD_APPROVED: Yes; FPLIST: RC0402_25,RC0402_HD,RC0402_X2,0402_CC; HEIGHT: 0.45 MM; MFG_NAME01: ROHM; MFG_PN01: MCR01MZPJ000; ROHS: Yes; Tolerance: 5%; VOLTAGE: 1/16W
R14 = RES: RES MF 10K 1/16W 1% 0402; AGILE_PN: 470-80452; ASSY_OPT: DNP; CAD_APPROVED: Yes; FPLIST: RC0402_25,RC0402_HD,0402_CC; HEIGHT: 0.40 MM; MFG_NAME01: NIC COMPONENTS CORP; MFG_PN01: NRCL04F1002TRF; ROHS: Yes; Tolerance: 1%
R15 R30 = RES: RES MF 4.99K 1/16W 1% 0402; AGILE_PN: 470-81149; CAD_APPROVED: Yes; FPLIST: RC0402_25,RC0402_HD,0402_CC; HEIGHT: 0.4 MM; MFG_NAME01: YAGEO AMERICA; MFG_PN01: RC0402FR-074K99L; ROHS: Yes; Tolerance: 1%
R19 R25 = RES: RES TF ZERO OHM 1/10W 5% 0603; AGILE_PN: 470-81264; CAD_APPROVED: Yes; FPLIST: RC0603_OV,RC0603,R603-X2,0603_CC; HEIGHT: 0.55MM; MFG_NAME01: YAGEO AMERICA; MFG_PN01: RC0603JR-070RL; ROHS: Yes; Temp Range: -55°C ~ 155°C; Temp_Range: -55°C ~ 155°C; Tolerance: 5%; VOLTAGE: 75V
R20 R24 = RES: RES MF 100 OHM 1/16W 1% 0402; AGILE_PN: 470-30454; CAD_APPROVED: Yes; FPLIST: RC0402_25,RC0402_HD,0402_CC; HEIGHT: 0.4 MM; MFG_NAME01: THYE MING TECH CO LTD; MFG_PN01: CR-02FL6--100R; ROHS: Yes; TOL: 1%; Tolerance: 1%; VOLTAGE: 50V
R27 R34 = RES: RES MF 2K 1/8W 1% 0805; AGILE_PN: 470-76341; CAD_APPROVED: Yes; FPLIST: RC0805_OV,RC0805,0805_CC; HEIGHT: 0.65MM; MFG_NAME01: BOURNS; MFG_PN01: CR0805-FX-2001ELF; ROHS: Yes; Tolerance: 1%
R28 R35 R58 R74 R81 = RES: RES MF ZERO OHM 1/16W 5% 0402; AGILE_PN: 470-75394; CAD_APPROVED: Yes; FPLIST: RC0603_OV,RC0603,R603-X2,0603_CC; HEIGHT: 0.45 MM; MFG_NAME01: ROHM; MFG_PN01: MCR01MZPJ000; ROHS: Yes; Tolerance: 5%; VOLTAGE: 1/16W
R31 R51 R67 = RES: RES MF ZERO OHM 1/16W 5% 0402; AGILE_PN: 470-75394; ASSY_OPT: DNP; CAD_APPROVED: Yes; FPLIST: RC0402_25,RC0402_HD,RC0402_X2,0402_CC; HEIGHT: 0.45 MM; MFG_NAME01: ROHM; MFG_PN01: MCR01MZPJ000; ROHS: Yes; Tolerance: 5%; VOLTAGE: 1/16W
R39 R60 = RES: RES MF 10.0K 1/16W 1% AEC-Q200 0402; AGILE_PN: 470-75416; ASSY_OPT: DNP; CAD_APPROVED: Yes; FPLIST: RC0402_25,RC0402_HD,0402_CC; HEIGHT: 0.4MM; MFG_NAME01: KOA SPEER; MFG_PN01: RK73H1ETTP1002F; PRIORITY_PN: 006-00552; ROHS: Yes; TOL: 1%; Temp Range: –55 °C to +155 °C; Temp_Range: –55 °C to +155 °C; Tolerance: 1%
R41 R44 = RES: RES MF 2.2K 1/16W 5% 0402; AGILE_PN: 470-76602; CAD_APPROVED: Yes; FPLIST: RC0402_25,RC0402_HD,0402_CC; HEIGHT: 0.4 MM; MFG_NAME01: YAGEO AMERICA; MFG_PN01: RC0402JR-072K2L; ROHS: Yes; Tolerance: 5%
R73 R77 = RES: RES MF 60.4 OHM 1/8W 1% 0805; AGILE_PN: 470-77684; CAD_APPROVED: Yes; FPLIST: RC0805_OV,RC0805,0805_CC; HEIGHT: 0.6MM; MFG_NAME01: YAGEO AMERICA; MFG_PN01: 232273466049L; ROHS: Yes; Tolerance: 1%; VOLTAGE: 150V
R75 = RES: RES MF 220 OHM 1/10W 5% 0603; AGILE_PN: 470-30297; CAD_APPROVED: Yes; FPLIST: RC0603_OV,RC0603,0603_CC; HEIGHT: 0.6MM; MFG_NAME01: YAGEO AMERICA; MFG_PN01: RC0603JR-07220RL; ROHS: Yes; Tolerance: 5%
R87 = RES: RES MF 470 OHM 1/16W 1% 0402; AGILE_PN: 470-76469; CAD_APPROVED: Yes; FPLIST: RC0402_25,RC0402_HD,0402_CC; HEIGHT: 0.4 MM; MFG_NAME01: THYE MING TECH CO LTD; MFG_PN01: CR-02FL6--470R; ROHS: Yes; Tolerance: 1%; VOLTAGE: 50V
RT1 = THERMISTOR: THERMISTOR 10K 1/10W 1% 0603; AGILE_PN: 470-80022; CAD_APPROVED: Yes; FPLIST: RC0603_OV,RC0603,0603_CC; HEIGHT: 0.33MM; MFG_NAME01: MuRata; MFG_PN01: NCP18XH103F03RB; ROHS: Yes; TOL: 1%; Tolerance: 1%
U3 = AT45DB021E_9P: IC MEM DATA FLASH 4MBIT SPI 85MHZ 1.65-3.6V UDFN8; AGILE_PN: 342-00652; CAD_APPROVED: Yes; HEIGHT: 0.6MM; MFG_NAME01: ADESTO TECHNOLOGIES CORPORATION, INC; MFG_PN01: AT45DB041E-MHN-Y; ROHS: Yes; VOLTAGE: 1.65-3.6V
U10 = TJA1027T_8P: IC XCVR LIN 5-18V AEC-Q100 SOIC8; AGILE_PN: 312-81255; CAD_APPROVED: Yes; HEIGHT: 1.75MM; MFG_NAME01: NXP SEMICONDUCTORS; MFG_PN01: TJA1027T/20,118; ROHS: Yes; VOLTAGE: 5-18V
U11 = FXOS8700CQ_QFN_16P: IC ACCELEROMETER AND MAGNETOMETER SENSOR 3-AXIS 2.5V QFN16; AGILE_PN: 312-80418; CAD_APPROVED: Yes; FPLIST: QFN5X3_0P5_3X3,QFN5X3_0P5_3X3_a; HEIGHT: 1.25MM; MFG_NAME01: FREESCALE SEMICONDUCTOR; ROHS: Yes; VOLTAGE: 2.5V
U15 = LD1117AS18: IC VREG LDO 5V 1A 20V SOT223; AGILE_PN: 315-79374; CAD_APPROVED: Yes; HEIGHT: 1.8MM; MFG_NAME01: ON SEMICONDUCTOR; ROHS: Yes; VOLTAGE: 5V
U19 = TJA1057GT3_8P: IC XCVR CAN 4.75-5.25V/2.95-5.25V AEC-Q100 SO8; AGILE_PN: 312-81479; CAD_APPROVED: Yes; HEIGHT: 1.75MM; MFG_NAME01: NXP SEMICONDUCTORS; ROHS: Yes; VOLTAGE: 4.75-5.25V/2.95-5.25V

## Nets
GND: C1.2 C2.2 C3.2 C4.2 C5.2 C6.2 C7.2 C8.2 C9.2 C10.2 C11.2 C12.2 C13.2 C14.2 C16.2 C17.2 C18.2 C19.2 C20.2 C22.2 C23.2 C24.2 C25.2 C26.2 C27.2 C28.2 C29.2 C30.2 C31.2 C32.2 C33.2 C34.2 C35.2 C37.2 C38.2 C39.2 C41.2 C42.2 C43.2 C48.2 C49.2 C53.2 C54.2 C59.2 C61.2 C62.2 C63.1 C68.2 D14.A D15.2(A2) D16.2(A2) J11.5(GND) J13.4 J14.3(A2) J14.5(A3) J23.4 J32.2 J32.3 J32.SH1(SHIELD1) J32.SH2(SHIELD2) Q1.2(SOURCE) Q2.2(SOURCE) Q3.2(SOURCE) Q4.2(SOURCE) R4.2 R15.2 R31.2 R49.2 R51.2 R57.2 R62.2 R64.1 R75.2 R80.1 R85.2 R94.1 R98.1 R101.2 SW1.1(S1) SW1.G1(GND1) SW1.G2(GND2) SW1.G3(GND3) SW1.G4(GND4) SW2.2(S2) SW2.G1(GND1) SW2.G2(GND2) SW2.G3(GND3) SW2.G4(GND4) SW3.2(S2) SW3.G1(GND1) SW3.G2(GND2) SW3.G3(GND3) SW3.G4(GND4) U1.4(GND) U3.7(GND) U3.9(EP) U4.2(GND) U5.2(VSS1) U5.8(VSSA) U5.33(EPAD) U6.3(DIR) U6.4(GND) U7.3(DIR) U7.4(GND) U8.2(GND) U9.2(GND) U10.5(GND) U11.3(RSVD1) U11.5(GND1) U11.12(GND2) U11.13(RSVD2) U12.2(GND) U13.2(GND) U14.2(GND) U15.1(GND) U17.2(GND) U19.2(GND) U19.8(S) U20.2(GND) U20.5(DIR) X1.2 ; also on sheet 4 6
P1V8_3V3_BRD: C13.1 C22.1 C31.1 C35.1 C49.1 C62.1 R9.1 R14.1 R17.1 R21.1 R30.1 R32.1 R36.1 R39.1 R41.1 R44.1 R46.1 R60.1 SH17.2 U3.6(VCC) U7.8(VCCB) U11.1(VDDIO) U12.6(VCCB) U17.6(VCCB) U20.6(VCCB) ; also on sheet 4 6
P3V3_LDO: C38.1 C39.1 U11.14(VDD) ; also on sheet 4
P3V3_SDA: C3.1 C8.1 C9.1 C10.1 C11.1 C20.1 C25.1 C29.1 C42.1 C43.1 J14.1(A1) R1.2 R5.1 R8.1 R10.1 R16.1 R38.1 R42.1 R43.1 R55.1 R65.1 R66.1 SH16.1 U1.1(VCCA) U4.1(VCCA) U5.1(VDD1) U5.7(VDDA) U5.11(VBAT) U6.7(VCCA) U8.5(VCC) U13.1(VCCA) U14.1(VCCA)
P5V: C24.1 C32.1 C41.1 C53.1 C54.1 C59.1 C61.1 R45.2 R50.1 R54.2 R71.1 U7.7(VCCA) U12.1(VCCA) U15.2(VOUT) U15.4(TAB) U17.1(VCCA) U19.3(VCC) U19.5(VIO) U20.1(VCCA) ; also on sheet 4
P5V0_SDA_USB_CONN_VBUS: D14.C J11.1(VBUS) L1.1 TP5.1(Pin1)
P5V_SDA: C5.1 C21.1 C27.1 L1.2 R48.1 R52.1 R56.1 TP35.1(Pin1) U5.6(VREGIN) U9.1(VIN)
P5V_SDA_PSW: TP29.1(Pin1) U9.6(VOUT) ; also on sheet 4 6
P12V: D11.A(ANODE) J13.2 J23.3 J32.1
P12V_VBAT: C33.1 C48.1 C68.1 D2.A D11.C(CATHODE) U10.7(VBAT) U15.3(VIN)
ADC0_DM0/CMP0_IN1: R19.1 ; also on sheet 4 6
ADC0_DP0/CMP0_IN0: R25.1 ; also on sheet 4 6
BYP_FXOS8700CQ: C34.1 U11.2(BYP)
CAN_HI: J23.1 R77.2 U19.7(CANH)
CAN_LO: J23.2 R73.1 U19.6(CANL)
CAN_RX: U17.3(A) U19.4(RXD)
CAN_TX: U19.1(TXD) U20.3(A)
CRST_FXOS8700CQ: C19.1 U11.8(CRST)
CS: R21.2 R23.2 TP14.1(Pin1) U3.4(~{CS})
I2C1_SCL: R44.2 R47.1 TP20.1(Pin1) U11.4(SCL/SCLK)
I2C1_SDA: R37.1 R41.2 TP17.1(Pin1) U11.6(SDA/MOSI)
INT1_COMBO_R: R61.1 U11.11(INT1)
INT2_COMBO: R39.2 R40.2 TP32.1(Pin1)
INT2_COMBO_R: R40.1 U11.9(INT2)
LEDRGB_BLUE: LED4.3(BLUE_C) R93.2
LEDRGB_GREEN: LED4.4(GREEN_C) R90.2
LEDRGB_RED: LED4.1(RED_C) R87.2
LIN: C28.1 J13.1 R27.1 R34.1 U10.6(LIN)
LIN_RX_LS: R54.1 U10.1(RXD) U12.3(A)
LIN_SLP: R45.1 U7.6(1A) U10.2(~{SLP})
LIN_TX_LS: U7.5(2A) U10.4(TXD)
LVLRST_EN: R1.1 U1.5(OE)
MIC2005_CSLEW: C21.2 U9.5(CSLEW)
P_LED: LED2.A(ANODE) LED3.A(ANODE) LED4.2(COMMON_A) ; also on sheet 4
POWER_EN: R53.1 U5.31(ADC0_SE7B/PTD6/SPI0_PCS3/UART0_RX/FTM0_CH6/FTM0_FLT0/LLWU_P15)
PTA0/SWD_DIO: J16.2 ; also on sheet 4
PTA16: R82.2 ; also on sheet 4 6
PTA17: R58.2 ; also on sheet 4 6
PTA18: R28.2 ; also on sheet 4 6
PTA19: R60.2 R61.2 ; also on sheet 4 6
PTB0: R47.2 ; also on sheet 4 6
PTB1: R37.2 ; also on sheet 4 6
PTB2: R89.2 ; also on sheet 4 6
PTB3: R92.1 ; also on sheet 4 6
PTB18: C7.1 R9.2 SW2.1(S1) TP6.1(Pin1) ; also on sheet 4 6
PTC1: R76.1 ; also on sheet 4 6
PTC2: C23.1 R36.2 SW3.1(S1) TP18.1(Pin1) ; also on sheet 4
PTC3: R81.2 ; also on sheet 4 6
PTC4: R74.2 ; also on sheet 4 6
PTC5: R35.2 ; also on sheet 4 6
PTC16: R13.1 ; also on sheet 4 6
PTC17: R11.1 ; also on sheet 4 6
PTC18: R12.2 ; also on sheet 4 6
PTC19: R23.1 ; also on sheet 4 6
RST_FXOS8700CQ: R64.2 R67.1 U11.16(RST)
RST_TGTMCU_b: J5.3 R2.2 R3.2 R67.2 U1.7(B1) ; also on sheet 4 6
SA0_FXOS8700CQ: R31.1 R32.2 U11.7(SA0/MISO)
SA1_FXOS8700CQ: R46.2 R51.1 U11.10(SA1/~{CS})
SCK: R13.2 R14.2 TP11.1(Pin1) U3.2(SCK)
SDA_EXTAL: C18.1 U5.17(EXTAL0/PTA18/FTM0_FLT2/FTM_CLKIN0) X1.3
SDA_JTAG_TCLK: J14.4(B2) U5.12(JTAG_TCLK/SWD_CLK/EZP_CLK/TSI0_CH1/PTA0/~{UART0_CTS}/~{UART0_COL}/FTM0_CH5)
SDA_JTAG_TDI: J14.8(B4) U5.13(JTAG_TDI/EZP_DI/TSI0_CH2/PTA1/UART0_RX/FTM0_CH6)
SDA_JTAG_TDO: J14.6(B3) U5.14(JTAG_TDO/TRACE_SWO/EZP_DO/TSI0_CH3/PTA2/UART0_TX/FTM0_CH7)
SDA_JTAG_TMS: J14.2(B1) R66.2 U5.15(JTAG_TMS/SWD_DIO/TSI0_CH4/PTA3/~{UART0_RTS}/FTM0_CH0)
SDA_LED: D1.C(CATHODE) TP8.1(Pin1) U5.29(PTD4/SPI0_PCS1/~{UART0_RTS}/FTM0_CH4/EWM_IN/LLWU_P14)
SDA_LED_R: D1.A(ANODE) R10.2
SDA_RST: J14.10(B5) R48.2 R49.1 TP34.1(Pin1) U5.19(~{RESET})
SDA_RST_LED: LED1.A(ANODE) R8.2
SDA_RST_TGTMCU_B: J6.2 U5.21(ADC0_SE9/TSI0_CH6/PTB1/I2C0_SDA/FTM1_CH1/FTM1_QD_PHB)
SDA_RST_TGTMCU_J_B: J5.1 J6.1 LED1.C(CATHODE) R3.1 R5.2 U1.2(A1)
SDA_RX_EN: R16.2 U4.5(DIR)
SDA_SPI0_SCK: TP37.1(Pin1) U5.26(PTC5/SPI0_SCK/LPTMR0_ALT2/I2S0_RXD0/CMP0_OUT/LLWU_P9) U14.3(A)
SDA_SPI0_SIN: TP28.1(Pin1) U5.28(CMP0_IN1/PTC7/SPI0_SIN/USB_SOF_OUT/I2S0_RX_FS) U6.5(2A)
SDA_SPI0_SOUT: TP33.1(Pin1) U5.27(CMP0_IN0/PTC6/SPI0_SOUT/PDB0_EXTRG/I2S0_RX_BCLK/I2S0_MCLK/LLWU_P10) U13.3(A)
SDA_SWD_EN: R65.2 U8.6(~{Y1}) U14.5(DIR)
SDA_SWD_EN_B: R43.2 U5.16(~{NMI}/~{EZP_CS}/TSI0_CH5/PTA4/FTM0_CH1/LLWU_P3) U8.1(A1)
SDA_SWD_OE: R55.2 U8.4(~{Y2}) U13.5(DIR)
SDA_SWD_OE_B: R42.2 U5.20(ADC0_SE8/TSI0_CH0/PTB0/I2C0_SCL/FTM1_CH0/FTM1_QD_PHA/LLWU_P5) U8.3(A2)
SDA_USB_CONN_DN: D16.1(A1) J11.2(D-) R22.1 TP12.1(Pin1)
SDA_USB_CONN_DP: D15.1(A1) J11.3(D+) R18.1 TP7.1(Pin1)
SDA_USB_DN: R22.2 U5.4(USB0_DM)
SDA_USB_DP: R18.2 U5.3(USB0_DP)
SDA_USB_P5V_SENSE: R56.2 R62.1 TP24.1(Pin1) U5.30(ADC0_SE6B/PTD5/SPI0_PCS2/~{UART0_CTS}/~{UART0_COL}/FTM0_CH5/~{EWM_OUT})
SDA_VOUT33: C6.1 SH16.2 U5.5(VOUT33)
SDA_XTAL: C16.1 U5.18(XTAL0/PTA19/FTM1_FLT0/FTM_CLKIN1/LPTMR0_ALT1) X1.1
SI: R11.2 TP9.1(Pin1) U3.1(SI)
SO: R12.1 TP10.1(Pin1) U3.8(SO)
SW1_RST_B: C4.1 J5.2 SW1.2(S2)
SWD_CLK_TGTMCU: J17.2 ; also on sheet 4
SWD_CLK_TGTMCU_BUF: J17.1 U14.4(B)
SWD_DIO_TGTMCU_BUF: J16.1 U6.2(2B) U13.4(B)
TC_EXTAL_TP: TP31.1(Pin1) U5.10(EXTAL32)
TC_XTAL_TP: TP30.1(Pin1) U5.9(XTAL32)
THER_A: C15.1 R24.1 R30.2 RT1.1
THER_B: C15.2 R15.1 R20.1 RT1.2
TP_2102_A: TP2.1(Pin1) U1.3(A2)
TP_2102_B: TP1.1(Pin1) U1.6(B2)
UART0_RX_TGTMCU: R26.2 ; also on sheet 4 6
UART0_TX_TGTMCU: R29.2 ; also on sheet 4 6
UART1_CTS_TGTMCU_R: U5.23(ADC0_SE4B/CMP1_IN0/TSI0_CH15/PTC2/SPI0_PCS2/~{UART1_CTS}/FTM0_CH1/I2S0_TX_FS)
UART1_RTS_TGTMCU_R: U5.22(ADC0_SE15/TSI0_CH14/PTC1/SPI0_PCS3/~{UART1_RTS}/FTM0_CH0/I2S0_TXD0/LLWU_P6)
UART1_RX_TGTMCU_BUF: R26.1 TP15.1(Pin1) U4.4(B)
UART1_RX_TGTMCU_R: TP27.1(Pin1) U4.3(A) U5.25(PTC4/SPI0_PCS0/UART1_TX/FTM0_CH3/CMP1_OUT/LLWU_P8)
UART1_TX_TGTMCU_BUF: R29.1 R33.2 TP16.1(Pin1) U6.1(1B)
UART1_TX_TGTMCU_R: TP26.1(Pin1) U5.24(CMP1_IN1/PTC3/SPI0_PCS1/UART1_RX/FTM0_CH2/I2S0_TX_BCLK/LLWU_P7) U6.6(1A)
V_TGTMCU: C1.1 C12.1 C26.1 C30.1 C37.1 R2.1 R33.1 SH17.1 U1.8(VCCB) U4.6(VCCB) U6.8(VCCB) U13.6(VCCB) U14.6(VCCB)
VTRG_EN: R52.2 R53.2 R57.1 U9.3(ENABLE)
VTRG_FAULT_B: R38.2 TP23.1(Pin1) U5.32(PTD7/CMT_IRO/UART0_TX/FTM0_CH7/FTM0_FLT1) U9.4(~{FAULT})
WP/RST: R17.2 U3.3(~{RESET}) U3.5(~{WP})
N21167890: C2.1 J11.6(SHELL1) J11.7(SHELL2) J11.8(SHELL3) J11.9(SHELL4) R4.1
N21328439: C17.1 R24.2 R25.2
N21328458: C14.1 R19.2 R20.2
N21328514: Q4.3(DRAIN) R88.1
N21337706: D2.C R27.2 R34.2
N21361580: C63.2 R73.2 R77.1
N21445715: J11.4(ID) TP13.1(Pin1)
N21455862: Q1.1(GATE) R76.2 R80.2
N21456098: Q1.3(DRAIN) R87.1
N21456788: Q2.1(GATE) R82.1 R85.1
N21456802: Q2.3(DRAIN) R90.1
N21456812: Q3.1(GATE) R89.1 R94.2
N21456830: Q3.3(DRAIN) R93.1
N21501528: Q4.1(GATE) R92.2 R98.2
N21560793: R35.1 U7.1(1B)
N21560827: J39.1 R50.2
N21560833: R58.1 U12.4(B)
N21560903: R28.1 U7.2(2B)
N21561545: R71.2 U17.5(DIR)
N21561559: R74.1 U17.4(B)
N21611491: R81.1 U20.4(B)
N21928909: J39.2 U12.5(DIR)
N21929178: J39.3 R101.1
N22227084: LED2.C(CATHODE) R75.1
N22227091: LED3.C(CATHODE) R88.2

Not connected (* = marked no-connect by the designer): J13 3*; J14 7(A4)* 9(A5)*; U10 3(NC1)* 8(NC2)*; U11 15(NC)*

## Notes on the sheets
sheet 1
- CAN/LIN Power
- Note: P12V is alternative input power supply from J23, J32 or J13.
- INTERRUPT PUSH BUTTONS
- External 12V
- CAN
- THERMISTOR
- Note: P12V is alternative input power supply from J23, J32 or J13.
- LIN
- CAD Note: Close the passive filter close to ADC input pin
- Only for master mode
- RGB LED
- Note: P12V is alternative input power supply from J23, J32 or J13.
- FXOS8700CQ COMBO SENSOR
- POWER ON/
  COMMUNICATING
- Note: when running from a low
  voltage battery (i.e., when the
  MCU is to be in buck mode)
  the accelerometer will not
  operate unless the DCDC output
  voltage is increased to above
  2.0V.
- 4MBit (512KB) FLASH
sheet 2
- Table of Contents
- Revisions & Change Log
- 1
- Title
- Rev
- Description
- Date
- Approved
- 2
- Block Diagram
- X1
- First Release
- 12/20/18
- 3
- MKW38A MCU
- X2
- J39 added for CAN/LIN
  DIR pin
- 01/08/19
- 4
- OpenSDA INTERFACE
- A
- Prototype Release
- 01/24/19
- 5
- Sensor, CAN, LIN,  Misc
- B
- Sensor VDD to 3V3
  Layout implementations
  RF matching update
- 07/08/19
- M.Baudry
- 6
- I/O Headers and Power Supply
- B1
- RF optimization (BOM)
- 10/15/19
- FREEDOM KW38
  Bluetooth Smart/Generic FSK
sheet 3
- RESET
- OpenSDA Interface
- 1-2: Default.
  2-3: Reset signal direct to the MCU,
  to use when OpenSDA is not powered.
- RST Push Button
  Bypass
- TARGET MCU
  INTERFACE
  SIGNALS
- SHORTING HEADER
  ON BOTTOM LAYER
- CAD Note: Place 33 Ohm
  resistor close to MCU pin
- Output to system
  from Level shifter
- CAD Note: Add 20 millohm
  drawn resistor
- Isolation
  Resistors
- Output to system
  from Level shifter
- Note: Pullup prevents random
  output on terminal before UART
  is configured.
- PU/PD LOGIC:
  SERIAL INTERFACE
  IS ALWAYS RESET
  WHEN USB PORT
  IS DISCONNECTED
- Input to Level shifter
  from system
- SHORTING HEADER
  ON BOTTOM LAYER
- SHORTING HEADER
  ON BOTTOM LAYER
- HW Designer: Rafael del Rey
- OPEN SDA
  POWER OUTPUTS
- OPEN SDA
  INPUT POWER
- i
- path
- i
- path
- Note: You can power openSDA
  with your own power supplies
  by replacing this rail
  (SDA_VOUT33)
  with your 3.3V power supply rail
- 3.3VDC, 10mA should be provided
  to this rail (P3V3_SDA)
  in order to power openSDA
  module
- i
- path
- PWR SWITCH
- OpenSDA INTERFACE JTAG CONNECTOR
- (To enable 5v from
  USB connector)
- SDA_VOUT33 can provide up to 120mA
  of power at 3.3VDC to your system
  P5V_TRG_SDA can provide up to 450mA
  (per USB spec) of power at 5VDC
  to your system
- ACTIVE HIGH
- I/O POWER
  INPUT
- i
- path
- This power rail is supported
  from 1.8V to 5V
- Power should be provided
  to this rail for the logic
  related to your platform I/O
